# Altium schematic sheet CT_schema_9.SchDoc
size 278 x 170 mm
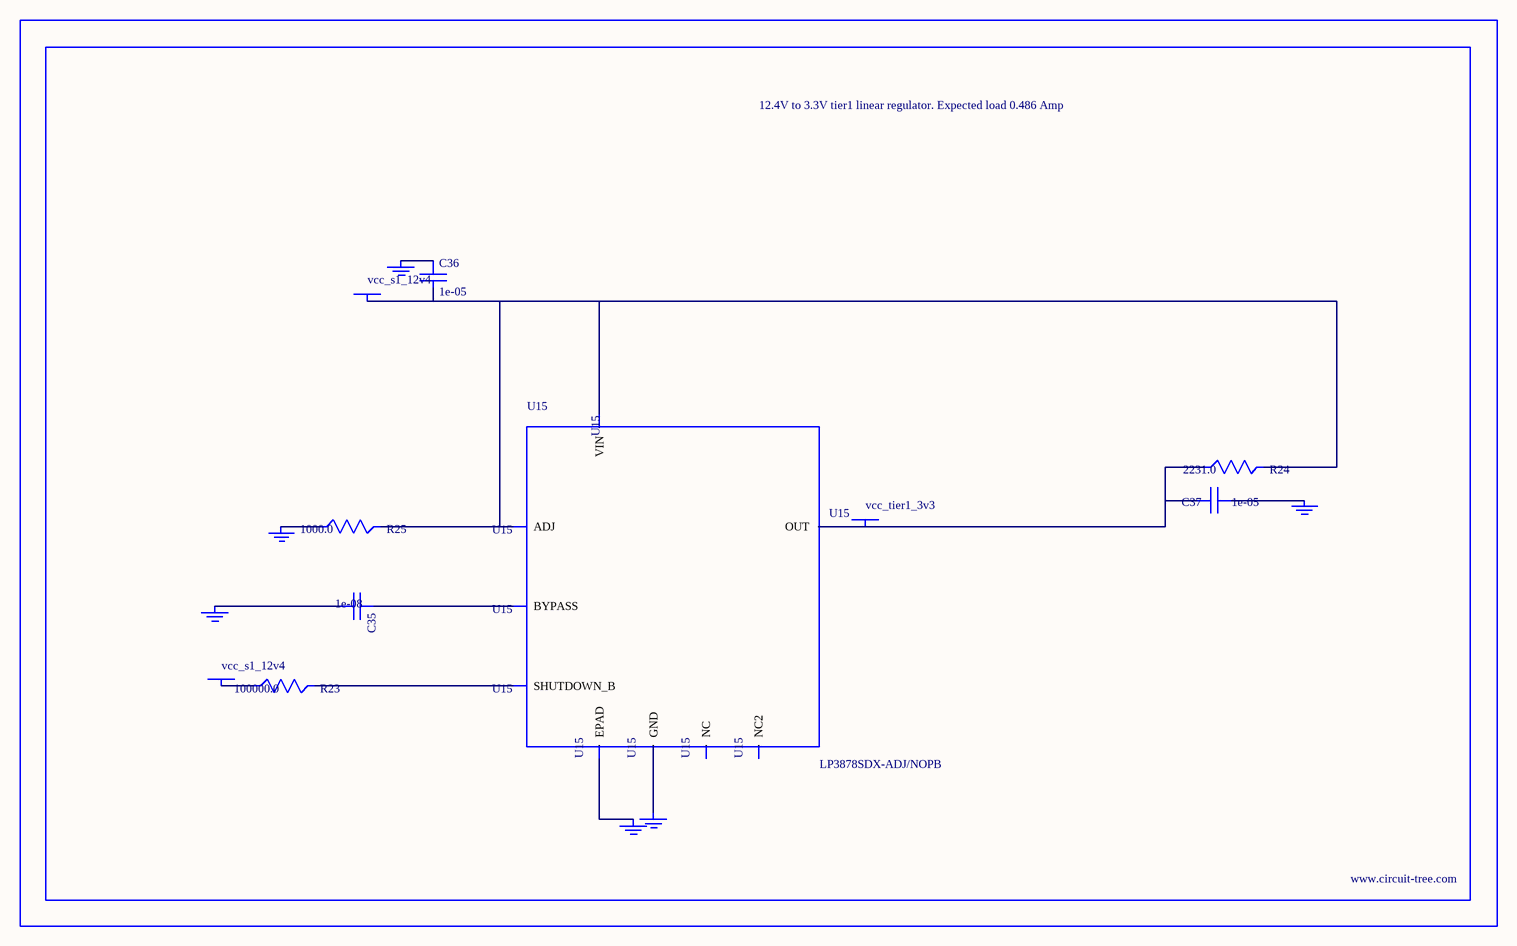
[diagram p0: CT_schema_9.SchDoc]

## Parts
BORDER8  (no value)
C35  1e-08  [C0402]
C36  1e-05  [C1210]
C37  1e-05  [C1210]
GND_INSTANCE_8_0  (no value)
GND_INSTANCE_8_1  (no value)
GND_INSTANCE_8_2  (no value)
GND_INSTANCE_8_3  (no value)
GND_INSTANCE_8_4  (no value)
GND_INSTANCE_8_5  (no value)
POWER_INSTANCE_8_0  vcc_s1_12v4
POWER_INSTANCE_8_1  vcc_s1_12v4
POWER_INSTANCE_8_2  vcc_tier1_3v3
R23  100000.0  [R0603]
R24  2231.0  [R0603]
R25  1000.0  [R0603]
U15  LP3878SDX-ADJ/NOPB  [WSON-8]

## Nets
NetC35_1: C35.1 U15.1(BYPASS)
NetC35_2: C35.2 GND_INSTANCE_8_0.0(GND)
NetC36_1: C36.1 GND_INSTANCE_8_1.0(GND)
NetC36_2: C36.2 POWER_INSTANCE_8_0.0(PWR) R24.2 R25.2 U15.4(VIN) U15.6(ADJ)
NetC37_1: C37.1 GND_INSTANCE_8_2.0(GND)
NetC37_2: C37.2 POWER_INSTANCE_8_2.0(PWR) R24.1 U15.5(OUT)
NetGND_INSTANCE_8_3_0: GND_INSTANCE_8_3.0(GND) R25.1
NetGND_INSTANCE_8_4_0: GND_INSTANCE_8_4.0(GND) U15.PAD(EPAD)
NetGND_INSTANCE_8_5_0: GND_INSTANCE_8_5.0(GND) U15.3(GND)
NetPOWER_INSTANCE_8_1_0: POWER_INSTANCE_8_1.0(PWR) R23.1
NetR23_2: R23.2 U15.8(SHUTDOWN_B)

Not connected (* = marked no-connect by the designer): U15 2(NC) 7(NC2)

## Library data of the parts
BORDER8 = BORDER_PAGE8
C35 = C0402C103K3RAC
C36 = C1210C106K5PACTU
C37 = GRM32DR61E106MA12L
GND_INSTANCE_8_0-GND_INSTANCE_8_5 = GND
POWER_INSTANCE_8_0-POWER_INSTANCE_8_2 = PWR
R23 = RC0603JR-07100KL
R24 = R24
R25 = RC0603JR-071KL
